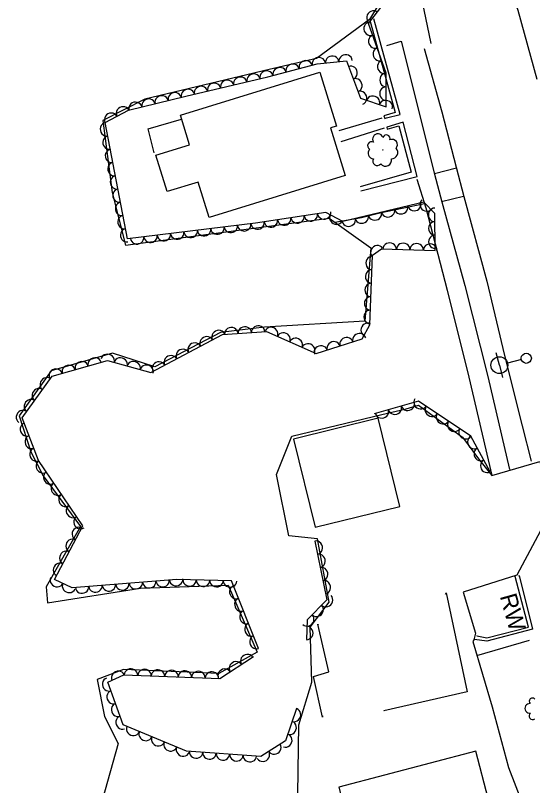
# Model space of a CAD drawing. Extents: x 1722896 to 1754269, y 648279 to 666297.
# Drawn here: x 1725871.6 to 1726025, y 664330.2 to 664558.8 of the extents above; entities that cross this region are included whole.
import ezdxf

# ---------------------------------------------------------------- set-up
doc = ezdxf.new("R2010")
doc.units = 0
for name, color, linetype in [('DESIGN - CENTERLINE - Proposed Text', 7, 'Continuous'), ('SURVEY - CENTERLINE - Preliminary', 7, 'Continuous'), ('SURVEY - CENTERLINE - Preliminary Text', 7, 'Continuous'), ('SURVEY - CONTROL with Text', 7, 'Continuous'), ('SURVEY - DTM - Breaklines', 7, 'Continuous'), ('SURVEY - VEGETATION - Features with Text', 7, 'Continuous')]:
    doc.layers.add(name, color=color, linetype=linetype)

msp = doc.modelspace()

# ---------------------------------------------------------------- linework, layer by layer
at = {"layer": 'DESIGN - CENTERLINE - Proposed Text'}
for points in [[(1725976.66, 664557.39), (1725984.21, 664529.96), (1725980.83, 664528.93), (1725981.11, 664528.23), (1725981.61, 664528.39)], [(1725981.61, 664528.39), (1725985.7, 664529.41), (1725977.91, 664557.79)], [(1725912.74, 664517.96), (1725910.9, 664525.08), (1725920.87, 664527.98)], [(1725967.6, 664524.61), (1725980.38, 664528.37)], [(1725968.2, 664521.37), (1725981.09, 664525.41)], [(1725974.07, 664506.76), (1725990.77, 664510.97), (1725986.57, 664527.08), (1725981.73, 664525.6), (1725981.88, 664525.06), (1725985.3, 664525.98), (1725988.95, 664512.29), (1725973.84, 664507.92)], [(1726021, 664392.6), (1726024.96, 664376.64), (1726011.37, 664373.08), (1726007.74, 664373.57), (1726007.84, 664373.7)], [(1726008.49, 664374.67), (1726011.39, 664374.07), (1726023.75, 664377.21), (1726019.86, 664392.23)], [(1726020.87, 664392.42), (1726021, 664392.6)], [(1725999.34, 664387.38), (1726005.55, 664358.1), (1725980.87, 664352.44), (1725980.94, 664352.56)], [(1725999.17, 664387.06), (1725999.34, 664387.38)], [(1725962.66, 664350.52), (1725960, 664362.63), (1725964.56, 664364.03), (1725961.32, 664378.1), (1725961.33, 664377.92)], [(1726008.55, 664374.78), (1726008.49, 664374.67)], [(1726008.47, 664368.84), (1726024.11, 664373.39)], [(1725962.64, 664350.93), (1725962.66, 664350.52)]]:
    msp.add_lwpolyline(points, dxfattribs=at)
for points in [[(1725961.85, 664541.96), (1725966.81, 664525.93), (1725965.06, 664525.38), (1725969.43, 664511.26), (1725929.08, 664498.77), (1725925.81, 664509.34), (1725916.57, 664506.48), (1725913.22, 664517.31), (1725923.21, 664520.4), (1725920.5, 664529.16)], [(1725954.03, 664433.07), (1725960.45, 664406.9), (1725985.61, 664413.08), (1725979.18, 664439.25)], [(1725968.15, 664299.92), (1726015.51, 664312.37), (1726008.14, 664340.42), (1725967.49, 664329.74), (1725968.5, 664325.93), (1725962.67, 664324.4), (1725963.42, 664321.54), (1725956.39, 664319.69), (1725959.37, 664308.35), (1725965.51, 664309.96)]]:
    msp.add_lwpolyline(points, close=True, dxfattribs=at)
at = {"layer": 'SURVEY - CENTERLINE - Preliminary'}
for points in [[(1725980.04, 664563.42), (1725976.58, 664557.53), (1725960.93, 664545.95), (1725946.85, 664542.75), (1725909.96, 664533.97), (1725897.51, 664527.56), (1725900.28, 664506.18), (1725904.25, 664490.64), (1725964.62, 664498.59), (1725976.97, 664489.76), (1725975.26, 664468.05), (1725945.45, 664466.31), (1725932.39, 664464.73), (1725912.97, 664454.51), (1725900.32, 664458.52), (1725882.18, 664453.33), (1725872.7, 664439.94), (1725876.12, 664429.31), (1725879.78, 664422.13), (1725890.87, 664407.07), (1725880.64, 664389.16), (1725881.07, 664384.44), (1725908.7, 664388.79), (1725934.7, 664389.72), (1725943.25, 664369.84), (1725931.86, 664363.49), (1725903.67, 664364.68), (1725895.78, 664361.7), (1725897.99, 664350.72), (1725902.04, 664342.74), (1725895.67, 664320.17)], [(1725955.28, 664320.84), (1725955.65, 664348.22), (1725959.52, 664360.92), (1725958.98, 664377.27), (1725964.6, 664384.7), (1725961.18, 664403.49), (1725952.67, 664404.3), (1725949.03, 664422.52), (1725953.56, 664433.9), (1725980.28, 664440.31), (1725987.49, 664441.99), (1725991.19, 664443.09)], [(1725991.19, 664443.09), (1726004.2, 664433.6), (1726008.98, 664427.22), (1726012.88, 664422.2), (1726027.13, 664426.44), (1726031.18, 664413.04), (1726020.27, 664392.69), (1726004.37, 664387.62), (1726008.07, 664375.49), (1726007.55, 664373.49), (1726007.26, 664372.95), (1726012.96, 664353.56), (1726017.88, 664335.55), (1726025.52, 664315.62)]]:
    msp.add_lwpolyline(points, dxfattribs=at)
at = {"layer": 'SURVEY - CENTERLINE - Preliminary Text'}
for points in [[(1725993.71, 664631.45), (1726000.55, 664608.01), (1726008.6, 664590.72), (1726016.13, 664572.76), (1726020.64, 664560.34), (1726026.29, 664539.82)], [(1725994.87, 664550.42), (1725987.18, 664587.63), (1725977.44, 664620.52)], [(1725981.72, 664549.89), (1725985.96, 664551.18), (1725995.91, 664511.65), (1725998.02, 664503.42), (1726004.93, 664478.6), (1726011.74, 664451.66), (1726018.16, 664423.98)], [(1725992.87, 664548.96), (1725998.05, 664530.15), (1726002.35, 664513.79), (1726004.56, 664504.99), (1726011.4, 664479.9), (1726016.61, 664457.88), (1726021.87, 664436.96), (1726024.53, 664426.49)], [(1726002.44, 664513.45), (1725995.89, 664511.72)], [(1725990.69, 664510.23), (1725993.33, 664501.69), (1725999.63, 664477.27), (1726006.04, 664451.39), (1726012.88, 664422.2)], [(1726004.54, 664505.08), (1725998, 664503.49)], [(1725992.96, 664502.87), (1725979.7, 664500.1), (1725974.22, 664498.75), (1725966.37, 664497.34)]]:
    msp.add_lwpolyline(points, dxfattribs=at)
at = {"layer": 'SURVEY - DTM - Breaklines'}
for p, q in [((1726015.14, 664454.99), (1726014.21, 664458.62)), ((1726015.14, 664454.99), (1726016.07, 664451.36)), ((1726021.68, 664456.66), (1726017.56, 664455.61))]:
    msp.add_line(p, q, dxfattribs=at)
for centre, radius in [((1726015.14, 664454.99), 2.5), ((1726023.13, 664457.03), 1.5)]:
    msp.add_circle(centre, radius, dxfattribs=at)
at = {"layer": 'SURVEY - VEGETATION - Features with Text'}
for points in [[(1725943.72, 664370.95), (1725935.67, 664390.95), (1725919.42, 664391.42), (1725888.37, 664388.93), (1725883.16, 664391.42), (1725891.54, 664407.28), (1725878.38, 664426.71), (1725873.55, 664439.39), (1725882.48, 664451.68), (1725898.89, 664456.37), (1725911.71, 664452.8), (1725932.99, 664464.1), (1725946.09, 664464.94), (1725960.77, 664458.43), (1725974.48, 664462.82), (1725976.73, 664466.92), (1725977.5, 664487.59), (1725980.14, 664489.46), (1725996.04, 664489.05), (1725995.97, 664500.04), (1725992.77, 664503.36), (1725968.68, 664497.63), (1725963.67, 664500.3), (1725942.74, 664497.08), (1725904.78, 664492.44), (1725898.22, 664527), (1725905.06, 664530.65), (1725922.15, 664534.81), (1725946.46, 664540.53), (1725961.05, 664544.36), (1725969.8, 664545.26), (1725973.96, 664534.2), (1725981.52, 664531.66), (1725981.54, 664541.68), (1725976.27, 664556.35), (1725981.65, 664563.26)], [(1726012.38, 664423.31), (1726006.65, 664433.92), (1725991.12, 664444.3), (1725978.04, 664440.5)], [(1725960.38, 664402.79), (1725963.95, 664385.37), (1725958.12, 664379.4), (1725957.9, 664373.55)], [(1725954.97, 664353.06), (1725951.68, 664343.47), (1725944.37, 664338.91), (1725922.28, 664340.41), (1725903.51, 664348.21), (1725899.02, 664360.89), (1725903.7, 664363.08), (1725932.17, 664362.04), (1725942.18, 664368.49)]]:
    msp.add_lwpolyline(points, dxfattribs=at)
msp.add_circle((1725980.56, 664518.8), 0.0553, dxfattribs=at)
for centre, radius, start, end in [((1725979.11, 664522.04), 1.58, 20.1681, 213.5878), ((1725981.61, 664522.2), 1.09, 340.1474, 158.893), ((1725977.24, 664520.1), 1.2, 62.7867, 240.1059), ((1725983.3, 664520.39), 1.58, 318.0312, 114.8201), ((1725977.91, 664517.91), 1.71, 138.0738, 264.9195), ((1725983.19, 664518.06), 1.81, 267.084, 44.6082), ((1725978.89, 664515.52), 1.32, 148.2327, 323.233), ((1725981.36, 664515.83), 1.79, 217.9798, 13.8183), ((1726024.98, 664355.23), 0.978, 45.1099, 223.8555), ((1726024.15, 664353.14), 1.42, 85.1306, 278.5503), ((1726025.03, 664350.88), 1.08, 127.7492, 305.0684)]:
    msp.add_arc(centre, radius, start, end, dxfattribs=at)
for centre, major_axis in [((1725977.69, 664558.19), (1.23, 1.58)), ((1725976.83, 664554.78), (-0.68, 1.88)), ((1725978.19, 664551.01), (-0.68, 1.88)), ((1725979.54, 664547.25), (-0.68, 1.88)), ((1725961.57, 664544.41), (1.99, 0.2)), ((1725965.54, 664544.82), (1.99, 0.2)), ((1725969.52, 664545.23), (1.99, 0.2)), ((1725949.95, 664541.44), (1.93, 0.51)), ((1725953.81, 664542.46), (1.93, 0.51)), ((1725957.68, 664543.47), (1.93, 0.51)), ((1725971.11, 664541.77), (0.7, -1.87)), ((1725980.89, 664543.48), (-0.68, 1.88)), ((1725942.18, 664539.52), (1.95, 0.46)), ((1725946.07, 664540.43), (1.95, 0.46)), ((1725981.54, 664539.6), (0, 2)), ((1725934.39, 664537.69), (1.95, 0.46)), ((1725938.29, 664538.6), (1.95, 0.46)), ((1725972.52, 664538.03), (0.7, -1.87)), ((1725922.71, 664534.95), (1.95, 0.46)), ((1725926.6, 664535.86), (1.95, 0.46)), ((1725930.5, 664536.77), (1.95, 0.46)), ((1725981.53, 664535.6), (0, 2)), ((1725914.94, 664533.06), (1.94, 0.47)), ((1725918.82, 664534), (1.94, 0.47)), ((1725973.93, 664534.28), (0.7, -1.87)), ((1725977.66, 664532.96), (1.9, -0.64)), ((1725907.16, 664531.16), (1.94, 0.47)), ((1725911.05, 664532.11), (1.94, 0.47)), ((1725981.46, 664531.68), (1.9, -0.64)), ((1725899.91, 664527.9), (1.76, 0.94)), ((1725903.44, 664529.78), (1.76, 0.94)), ((1725898.61, 664524.95), (-0.37, 1.96)), ((1725899.35, 664521.02), (-0.37, 1.96)), ((1725900.1, 664517.09), (-0.37, 1.96)), ((1725900.84, 664513.17), (-0.37, 1.96)), ((1725901.59, 664509.24), (-0.37, 1.96)), ((1725902.34, 664505.31), (-0.37, 1.96)), ((1725903.08, 664501.38), (-0.37, 1.96)), ((1725989.9, 664502.67), (-1.95, -0.46)), ((1725993.5, 664502.6), (-1.39, 1.44)), ((1725963.16, 664500.22), (-1.98, -0.3)), ((1725978.22, 664499.9), (-1.95, -0.46)), ((1725982.11, 664500.82), (-1.95, -0.46)), ((1725986, 664501.75), (-1.95, -0.46)), ((1725995.97, 664499.6), (-0.01, 2)), ((1725903.83, 664497.45), (-0.37, 1.96)), ((1725947.35, 664497.79), (-1.98, -0.3)), ((1725951.3, 664498.4), (-1.98, -0.3)), ((1725955.26, 664499), (-1.98, -0.3)), ((1725959.21, 664499.61), (-1.98, -0.3)), ((1725966.75, 664498.66), (-1.76, 0.94)), ((1725970.44, 664498.04), (-1.95, -0.46)), ((1725974.33, 664498.97), (-1.95, -0.46)), ((1725931.49, 664495.7), (-1.99, -0.24)), ((1725935.46, 664496.19), (-1.99, -0.24)), ((1725939.43, 664496.67), (-1.99, -0.24)), ((1725943.39, 664497.18), (-1.98, -0.3)), ((1725996, 664495.6), (-0.01, 2)), ((1725904.57, 664493.52), (-0.37, 1.96)), ((1725911.63, 664493.28), (-1.99, -0.24)), ((1725915.6, 664493.76), (-1.99, -0.24)), ((1725919.57, 664494.25), (-1.99, -0.24)), ((1725923.55, 664494.73), (-1.99, -0.24)), ((1725927.52, 664495.22), (-1.99, -0.24)), ((1725996.03, 664491.6), (-0.01, 2)), ((1725907.66, 664492.79), (-1.99, -0.24)), ((1725982.6, 664489.4), (2, -0.05)), ((1725986.6, 664489.3), (2, -0.05)), ((1725990.6, 664489.19), (2, -0.05)), ((1725994.59, 664489.09), (2, -0.05)), ((1725978.88, 664488.57), (1.63, 1.16)), ((1725977.42, 664485.29), (0.07, 2)), ((1725977.27, 664481.29), (0.07, 2)), ((1725977.12, 664477.29), (0.07, 2)), ((1725976.97, 664473.3), (0.07, 2)), ((1725976.82, 664469.3), (0.07, 2)), ((1725935.62, 664464.27), (2, 0.13)), ((1725939.61, 664464.52), (2, 0.13)), ((1725943.6, 664464.78), (2, 0.13)), ((1725947.47, 664464.33), (1.83, -0.81)), ((1725975.95, 664465.5), (0.96, 1.75)), ((1725928.25, 664461.58), (1.77, 0.94)), ((1725931.79, 664463.46), (1.77, 0.94)), ((1725951.13, 664462.71), (1.83, -0.81)), ((1725973.58, 664462.53), (1.9, 0.61)), ((1725924.72, 664459.71), (1.77, 0.94)), ((1725954.78, 664461.09), (1.83, -0.81)), ((1725958.44, 664459.46), (1.83, -0.81)), ((1725965.96, 664460.09), (1.9, 0.61)), ((1725969.77, 664461.31), (1.9, 0.61)), ((1725921.19, 664457.83), (1.77, 0.94)), ((1725962.15, 664458.88), (1.9, 0.61)), ((1725895.08, 664455.28), (1.92, 0.55)), ((1725898.93, 664456.36), (1.93, -0.54)), ((1725902.78, 664455.28), (1.93, -0.54)), ((1725917.66, 664455.95), (1.77, 0.94)), ((1725887.39, 664453.08), (1.92, 0.55)), ((1725891.24, 664454.18), (1.92, 0.55)), ((1725906.63, 664454.21), (1.93, -0.54)), ((1725910.49, 664453.14), (1.93, -0.54)), ((1725914.12, 664454.08), (1.77, 0.94)), ((1725883.54, 664451.98), (1.92, 0.55)), ((1725880.78, 664449.34), (1.18, 1.62)), ((1725878.43, 664446.1), (1.18, 1.62)), ((1725876.08, 664442.86), (1.18, 1.62)), ((1725987.98, 664443.39), (-1.92, -0.56)), ((1725991.73, 664443.89), (-1.66, 1.11)), ((1725873.73, 664439.63), (1.18, 1.62)), ((1725980.3, 664441.16), (-1.92, -0.56)), ((1725984.14, 664442.27), (-1.92, -0.56)), ((1725995.06, 664441.67), (-1.66, 1.11)), ((1725998.38, 664439.44), (-1.66, 1.11)), ((1725874.87, 664435.93), (-0.71, 1.87)), ((1726001.71, 664437.22), (-1.66, 1.11)), ((1725876.29, 664432.19), (-0.71, 1.87)), ((1726005.03, 664435), (-1.66, 1.11)), ((1726007.63, 664432.11), (-0.95, 1.76)), ((1725877.72, 664428.45), (-0.71, 1.87)), ((1726009.53, 664428.59), (-0.95, 1.76)), ((1725879.58, 664424.94), (-1.12, 1.66)), ((1726011.43, 664425.07), (-0.95, 1.76)), ((1725881.82, 664421.63), (-1.12, 1.66)), ((1725884.06, 664418.32), (-1.12, 1.66)), ((1725886.31, 664415), (-1.12, 1.66)), ((1725888.55, 664411.69), (-1.12, 1.66)), ((1725890.79, 664408.38), (-1.12, 1.66)), ((1725890.29, 664404.92), (0.93, 1.77)), ((1725888.42, 664401.38), (0.93, 1.77)), ((1725960.78, 664400.83), (0.4, -1.96)), ((1725886.55, 664397.84), (0.93, 1.77)), ((1725961.59, 664396.91), (0.4, -1.96)), ((1725884.69, 664394.31), (0.93, 1.77)), ((1725962.39, 664392.99), (0.4, -1.96)), ((1725883.83, 664391.1), (-1.8, 0.86)), ((1725907.27, 664390.44), (-1.99, -0.16)), ((1725911.26, 664390.76), (-1.99, -0.16)), ((1725915.25, 664391.08), (-1.99, -0.16)), ((1725919.24, 664391.4), (-1.99, -0.16)), ((1725923.23, 664391.31), (-2, 0.06)), ((1725927.23, 664391.19), (-2, 0.06)), ((1725931.23, 664391.08), (-2, 0.06)), ((1725935.23, 664390.97), (-2, 0.06)), ((1725963.19, 664389.07), (0.4, -1.96)), ((1725887.44, 664389.38), (-1.8, 0.86)), ((1725891.33, 664389.17), (-1.99, -0.16)), ((1725895.31, 664389.49), (-1.99, -0.16)), ((1725899.3, 664389.81), (-1.99, -0.16)), ((1725903.29, 664390.12), (-1.99, -0.16)), ((1725937, 664387.65), (-0.75, 1.86)), ((1725963.79, 664385.21), (-1.4, -1.43)), ((1725938.49, 664383.94), (-0.75, 1.86)), ((1725960.99, 664382.35), (-1.4, -1.43)), ((1725939.98, 664380.23), (-0.75, 1.86)), ((1725958.2, 664379.49), (-1.4, -1.43)), ((1725941.48, 664376.52), (-0.75, 1.86)), ((1725957.97, 664375.52), (-0.07, -2)), ((1725942.97, 664372.81), (-0.75, 1.86)), ((1725940.3, 664367.27), (1.68, 1.08)), ((1725936.93, 664365.11), (1.68, 1.08)), ((1725902.03, 664362.3), (1.81, 0.85)), ((1725905.85, 664363), (2, -0.07)), ((1725909.85, 664362.85), (2, -0.07)), ((1725913.85, 664362.71), (2, -0.07)), ((1725917.85, 664362.56), (2, -0.07)), ((1725921.84, 664362.41), (2, -0.07)), ((1725925.84, 664362.27), (2, -0.07)), ((1725929.84, 664362.12), (2, -0.07)), ((1725933.57, 664362.94), (1.68, 1.08)), ((1725899.25, 664360.25), (-0.67, 1.89)), ((1725900.58, 664356.48), (-0.67, 1.89)), ((1725901.91, 664352.71), (-0.67, 1.89)), ((1725954.32, 664351.17), (-0.65, -1.89)), ((1725903.25, 664348.94), (-0.67, 1.89)), ((1725953.02, 664347.38), (-0.65, -1.89)), ((1725906.48, 664346.97), (-1.85, 0.77)), ((1725910.18, 664345.44), (-1.85, 0.77)), ((1725951.73, 664343.6), (-0.65, -1.89)), ((1725913.87, 664343.9), (-1.85, 0.77)), ((1725917.56, 664342.37), (-1.85, 0.77)), ((1725948.4, 664341.43), (-1.7, -1.06)), ((1725921.26, 664340.83), (-1.85, 0.77)), ((1725925.17, 664340.21), (-2, 0.13)), ((1725945.01, 664339.31), (-1.7, -1.06)), ((1725929.16, 664339.94), (-2, 0.13)), ((1725933.15, 664339.67), (-2, 0.13)), ((1725937.14, 664339.4), (-2, 0.13)), ((1725941.13, 664339.13), (-2, 0.13))]:
    msp.add_ellipse(centre, major_axis=major_axis, ratio=0.940188, start_param=0, end_param=3.141593, dxfattribs=at)

# ---------------------------------------------------------------- texts
at = {"layer": 'SURVEY - CONTROL with Text'}
msp.add_text('RW', height=5, rotation=285.7054, dxfattribs=at).set_placement((1726015.23, 664386.44))

doc.saveas('drawing.dxf')
